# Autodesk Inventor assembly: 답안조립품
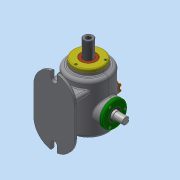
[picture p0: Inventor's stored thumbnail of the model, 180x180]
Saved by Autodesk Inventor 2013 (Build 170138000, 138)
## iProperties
Created: 2018-02
Part Number: 답안조립품
Document SubType Name: Assembly
Designer: dgall
Mass: 5400.16 g
Surface Area: 3901.7 cm^2
Volume: 1791.94 cm^3
Density: 3.01358 g/cm^3
Author: dgall
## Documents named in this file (16)
- C:\Users\dgall\Desktop\380207V1013\답안조립품.iam
- C:\Users\dgall\Desktop\380207V1013\본체.ipt
- C:\Users\dgall\Desktop\380207V1013\베어링 6205.ipt
- 베어링 6205.ipt
- C:\Users\dgall\Desktop\380207V1013\오일실.ipt
- 오일실.ipt
- C:\Users\dgall\Desktop\380207V1013\축 커버-1.ipt
- C:\Users\dgall\Desktop\380207V1013\편심축.ipt
- C:\Users\dgall\Desktop\380207V1013\축 커버-2.ipt
- C:\Users\dgall\Desktop\380207V1013\가변스프링.ipt
- C:\Users\dgall\Desktop\380207V1013\부시.ipt
- C:\Users\dgall\Desktop\380207V1013\슬라이드 커버.ipt
- C:\Users\dgall\Desktop\380207V1013\슬라이드.ipt
- C:\Users\dgall\Desktop\380207V1013\본체커버.ipt
- C:\Users\dgall\Desktop\380207V1013\상부 캡.ipt
- C:\Users\dgall\Desktop\380207V1013\볼트 M4.ipt
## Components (1 placed, 1 different names)
1. 가변스프링:1
